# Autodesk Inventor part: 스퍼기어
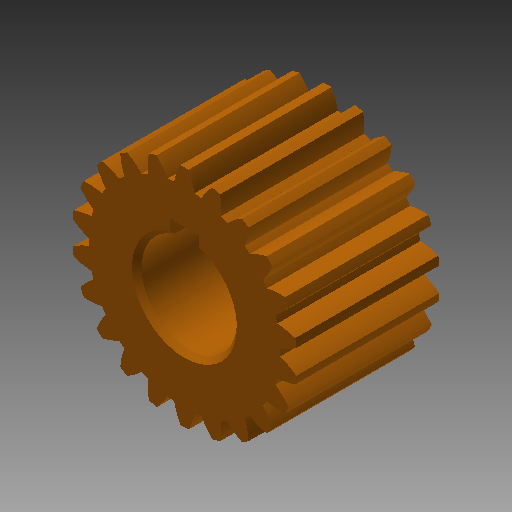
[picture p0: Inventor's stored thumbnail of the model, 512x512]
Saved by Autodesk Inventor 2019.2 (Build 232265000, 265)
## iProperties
Created: 2019-03
Part Number: 스퍼기어
Material: 강철
Document SubType Name: Modeling
Designer: mduedu
Categories: <?xml version="1.0" encoding="UTF-16"?> <MemberInstance><Categories><FamilyTemplate><FamilyTemplateParameter ValueType="xs:double" Id="1" ObjectReferenceKey="da
Density: 1 g/cm^3
Appearance: 주황색
CustomPartVersion: 1
Author: mduedu
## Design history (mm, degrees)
sketch "Sketch1"
  geometry: C1 r 23.6 at (0, 0)
  constraints: 1 centre point
  dimensions: "d0" = 47.2 diameter of C1 (= da_da)
extrude "Extrusion1" new body sketch "Sketch1" distance "d1" = 30 (= da_b); taper "d2" = 0 deg
workplane "Work Plane2"
sketch "Sketch2"
  geometry: C1 r 23.6 at (0, 0) reference; C2 r 22 at (0, 0)
  constraints: 1 centre point, 1 coincident
  dimensions: "d3" = 44 diameter of C2 (= da_dw)
feature "피치 지름" sketch "Sketch2" dims "d4" = 10, "d5" = 0
workplane "Work Plane8"
workplane "Work Plane9"
feature "스퍼 기어" dims "da_b" = 30, "da_d" = 44, "da_aw" = 44, "da_da" = 47.2, "da_df" = 40.172, "da_dw" = 44, angle "da_beta" = 0 deg, "da_lefttooth" = 0, "da_righttooth" = 0
sketch "스케치3"
  geometry: L1 (-3, 9.539)-(3, 9.539); L2 (3, 9.539)-(3, 12.8); L3 (3, 12.8)-(-3, 12.8); L4 (-3, 12.8)-(-3, 9.539); A1 r 10 centre (0, 0) between (-3, 9.539) and (3, 9.539); 1 further point
  constraints: 8 end point, 2 parallel, 2 point on circle, 1 centre point, 1 coincident, 1 horizontal, 1 perpendicular
  dimensions: "d49" = 20 diameter of A1; "d50" = 6 distance of L2.end L3.end; "d51" = 22.8 dimension on A1 L3
extrude "돌출2" cut sketch "스케치3" extent not by distance; stored distance "d52" = 10; taper "d53" = 0 deg
chamfer "모따기1" distance "d54" = 1; stored, may be unused: second distance "d55" = 2, angle "d56" = 45 deg
body "Solid1"
body "Srf1"
other parameters: "d16" = 44 (= da_aw), "d17" = 0, "d34" = 1.428 (computed from da_z), "d39" = 0, "d41" = 0, "d43" = 44 (= da_aw), "d46" = 44 (= da_aw), "d47" = 0, "d48" = 0
